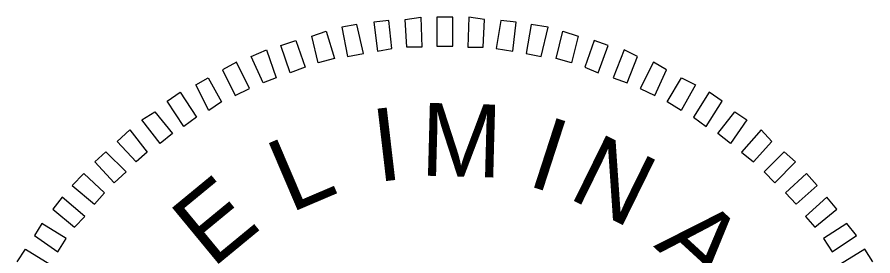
# Model space of a CAD drawing. Extents: x 16 to 1228743, y 11 to 152440.
# Drawn here: x 17.6758 to 17.8566, y 10.988 to 11.0385 of the extents above; entities that cross this region are included whole.
import ezdxf

# ---------------------------------------------------------------- set-up
doc = ezdxf.new("R2010")
doc.units = 0
doc.layers.add('STAMP_PRELIM', color=7, linetype='Continuous')

msp = doc.modelspace()

# ---------------------------------------------------------------- linework, layer by layer
at = {"layer": 'STAMP_PRELIM'}
for p, q in [((17.75431, 11.03776), (17.75113, 11.03743)), ((17.75496, 11.03181), (17.75431, 11.03776)), ((17.7578, 11.038), (17.76105, 11.03848)), ((17.75813, 11.03214), (17.7578, 11.038)), ((17.76105, 11.03848), (17.7613, 11.03214)), ((17.76781, 11.03848), (17.76447, 11.03848)), ((17.76447, 11.03848), (17.76447, 11.0323)), ((17.76781, 11.0323), (17.76781, 11.03848)), ((17.77123, 11.03848), (17.77098, 11.03214)), ((17.77456, 11.038), (17.77123, 11.03848)), ((17.77424, 11.03214), (17.77456, 11.038)), ((17.77798, 11.03776), (17.77701, 11.03181)), ((17.78124, 11.03743), (17.77798, 11.03776)), ((17.74755, 11.03694), (17.74438, 11.03637)), ((17.74438, 11.03637), (17.74559, 11.03018)), ((17.74893, 11.03076), (17.74755, 11.03694)), ((17.75113, 11.03743), (17.75194, 11.03125)), ((17.78051, 11.03125), (17.78124, 11.03743)), ((17.78442, 11.03694), (17.78335, 11.03076)), ((17.788, 11.03637), (17.78442, 11.03694)), ((17.78653, 11.03018), (17.788, 11.03637)), ((17.73803, 11.03442), (17.74104, 11.03548)), ((17.73941, 11.02881), (17.73803, 11.03442)), ((17.74104, 11.03548), (17.74283, 11.0297)), ((17.7897, 11.0297), (17.79109, 11.03548)), ((17.79109, 11.03548), (17.79434, 11.03442)), ((17.79434, 11.03442), (17.79288, 11.02881)), ((17.73152, 11.03246), (17.73469, 11.03353)), ((17.73347, 11.02669), (17.73152, 11.03246)), ((17.73469, 11.03353), (17.73664, 11.02791)), ((17.76447, 11.0323), (17.76781, 11.0323)), ((17.79768, 11.03353), (17.79572, 11.02791)), ((17.80069, 11.03246), (17.79768, 11.03353)), ((17.79858, 11.02669), (17.80069, 11.03246)), ((17.72525, 11.03018), (17.72843, 11.03157)), ((17.72843, 11.03157), (17.73054, 11.02563)), ((17.74559, 11.03018), (17.74893, 11.03076)), ((17.75194, 11.03125), (17.75496, 11.03181)), ((17.7613, 11.03214), (17.75813, 11.03214)), ((17.77098, 11.03214), (17.77424, 11.03214)), ((17.77701, 11.03181), (17.78051, 11.03125)), ((17.78335, 11.03076), (17.78653, 11.03018)), ((17.80402, 11.03157), (17.80174, 11.02563)), ((17.80688, 11.03018), (17.80402, 11.03157)), ((17.72216, 11.02897), (17.71915, 11.02734)), ((17.72485, 11.02335), (17.72216, 11.02897)), ((17.72778, 11.02457), (17.72525, 11.03018)), ((17.74283, 11.0297), (17.73941, 11.02881)), ((17.79288, 11.02881), (17.7897, 11.0297)), ((17.80467, 11.02457), (17.80688, 11.03018)), ((17.81021, 11.02897), (17.80744, 11.02335)), ((17.81298, 11.02734), (17.81021, 11.02897)), ((17.71915, 11.02734), (17.72183, 11.02188)), ((17.73664, 11.02791), (17.73347, 11.02669)), ((17.79572, 11.02791), (17.79858, 11.02669)), ((17.81053, 11.02188), (17.81298, 11.02734)), ((17.71353, 11.02416), (17.71613, 11.02563)), ((17.71613, 11.02563), (17.71899, 11.02058)), ((17.73054, 11.02563), (17.72778, 11.02457)), ((17.80174, 11.02563), (17.80467, 11.02457)), ((17.81314, 11.02058), (17.81615, 11.02563)), ((17.81615, 11.02563), (17.81908, 11.02416)), ((17.7163, 11.01871), (17.71353, 11.02416)), ((17.72183, 11.02188), (17.72485, 11.02335)), ((17.80744, 11.02335), (17.81053, 11.02188)), ((17.81908, 11.02416), (17.81607, 11.01871)), ((17.70751, 11.02067), (17.7102, 11.02262)), ((17.7102, 11.02262), (17.71369, 11.01733)), ((17.82201, 11.02262), (17.81867, 11.01733)), ((17.82478, 11.02067), (17.82201, 11.02262)), ((17.71101, 11.01537), (17.70751, 11.02067)), ((17.71899, 11.02058), (17.7163, 11.01871)), ((17.81607, 11.01871), (17.81314, 11.02058)), ((17.82136, 11.01537), (17.82478, 11.02067)), ((17.70214, 11.01676), (17.7049, 11.01847)), ((17.7049, 11.01847), (17.70857, 11.01383)), ((17.8238, 11.01383), (17.82739, 11.01847)), ((17.82739, 11.01847), (17.82999, 11.01676)), ((17.70597, 11.01172), (17.70214, 11.01676)), ((17.71369, 11.01733), (17.71101, 11.01537)), ((17.81867, 11.01733), (17.82136, 11.01537)), ((17.82999, 11.01676), (17.82648, 11.01172)), ((17.69693, 11.0122), (17.69962, 11.01465)), ((17.69962, 11.01465), (17.70328, 11.00993)), ((17.83299, 11.01465), (17.82885, 11.00993)), ((17.83527, 11.0122), (17.83299, 11.01465)), ((17.70857, 11.01383), (17.70597, 11.01172)), ((17.82648, 11.01172), (17.8238, 11.01383)), ((17.70092, 11.00789), (17.69693, 11.0122)), ((17.83137, 11.00789), (17.83527, 11.0122)), ((17.69221, 11.00789), (17.69449, 11.01)), ((17.69449, 11.01), (17.6988, 11.00577)), ((17.70328, 11.00993), (17.70092, 11.00789)), ((17.82885, 11.00993), (17.83137, 11.00789)), ((17.83788, 11.01), (17.83365, 11.00577)), ((17.84024, 11.00789), (17.83788, 11.01)), ((17.69628, 11.00342), (17.69221, 11.00789)), ((17.83585, 11.00342), (17.84024, 11.00789)), ((17.68985, 11.00537), (17.68741, 11.00284)), ((17.69425, 11.0013), (17.68985, 11.00537)), ((17.6988, 11.00577), (17.69628, 11.00342)), ((17.83365, 11.00577), (17.83585, 11.00342)), ((17.8426, 11.00537), (17.83813, 11.0013)), ((17.8448, 11.00284), (17.8426, 11.00537)), ((17.68741, 11.00284), (17.69213, 10.99893)), ((17.84041, 10.99893), (17.8448, 11.00284)), ((17.6853, 11.0004), (17.68334, 10.99788)), ((17.69009, 10.99633), (17.6853, 11.0004)), ((17.69213, 10.99893), (17.69425, 11.0013)), ((17.83813, 11.0013), (17.84041, 10.99893)), ((17.84683, 11.0004), (17.84236, 10.99633)), ((17.84895, 10.99788), (17.84683, 11.0004)), ((17.68334, 10.99788), (17.6879, 10.99405)), ((17.84431, 10.99405), (17.84895, 10.99788)), ((17.6879, 10.99405), (17.69009, 10.99633)), ((17.84236, 10.99633), (17.84431, 10.99405)), ((17.68098, 10.99479), (17.67944, 10.99226)), ((17.68611, 10.99161), (17.68098, 10.99479)), ((17.85106, 10.99479), (17.84618, 10.99161)), ((17.8531, 10.99226), (17.85106, 10.99479)), ((17.67944, 10.99226), (17.68439, 10.98884)), ((17.68439, 10.98884), (17.68611, 10.99161)), ((17.84618, 10.99161), (17.84797, 10.98884)), ((17.84797, 10.98884), (17.8531, 10.99226)), ((17.67577, 10.98673), (17.67756, 10.98942)), ((17.67756, 10.98942), (17.68269, 10.98624)), ((17.85489, 10.98942), (17.84976, 10.98624)), ((17.8566, 10.98673), (17.85489, 10.98942))]:
    msp.add_line(p, q, dxfattribs=at)

# ---------------------------------------------------------------- texts
for s, rotation, p in [('M', 358.4667, (17.76089, 11.00496)), ('I', 6.6752, (17.75186, 11.00358)), ('I', 342.0495, (17.78319, 11.003)), ('L', 23.0924, (17.73347, 10.99698)), ('N', 333.841, (17.7919, 11.00032)), ('E', 39.5095, (17.71703, 10.98519)), ('A', 317.4238, (17.81013, 10.98998))]:
    msp.add_text(s, height=0.01542, rotation=rotation, dxfattribs=at).set_placement(p)

doc.saveas('drawing.dxf')
